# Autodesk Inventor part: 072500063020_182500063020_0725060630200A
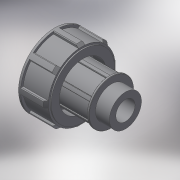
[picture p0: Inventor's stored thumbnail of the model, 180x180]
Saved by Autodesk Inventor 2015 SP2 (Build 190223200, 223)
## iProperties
Created: 2017-04
Part Number: 072500063020_182500063020_0725060630200A
Material: Generic
Description: PLASSON THREADED ADAPTOR 63-2"
Document SubType Name: Modeling
Designer: KIM
Density: 1 g/cm^3
Appearance: Default
Author: KIM
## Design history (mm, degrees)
derived "07250.ipt"
feature "Solid1::07250.ipt"
tag "TaggingFeature1"
body "Solid1"
other parameters: "d1" = 59.614, "d2" = 114, "d3" = 26, "d6" = 113, "d7" = 105.09, "d8" = 90.4, "d9" = 63, "d10" = 68.5561, "d12" = 35.7684, "d13" = 47.6912, "d14" = 29.9, "d15" = 84.75, "d16" = 3.42, "d17" = 45.6, "d18" = 26, "d19" = 31.2, "d24" = 11.9228, "d25" = 5.9614, "d27" = 0, "d28" = 4.76912, "d31" = 1.19228, "d35" = 360 deg, "d41" = 29.337, "d56" = 66.15, "d57" = 6.3, "d58" = 3.15, "d60" = 0, "d61" = 0.59614, "d64" = 0.59614, "d68" = 360 deg, "d_" = 63, "R_" = 59.614, "E_" = 113, "H_" = 114, "l_2" = 26, "d55" = 63
